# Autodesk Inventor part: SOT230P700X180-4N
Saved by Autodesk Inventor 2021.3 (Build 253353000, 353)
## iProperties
Created: 2021-12
Part Number: SOT230P700X180-4N
Material: Generic
Document SubType Name: Modeling
Designer: Administrator
Density: 1 g/cm^3
Appearance: Default
Title: SOT230P700X180-4N
Author: Administrator
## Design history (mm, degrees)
feature "Body1"
body "Solid1"
